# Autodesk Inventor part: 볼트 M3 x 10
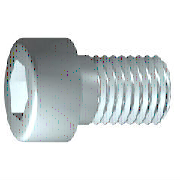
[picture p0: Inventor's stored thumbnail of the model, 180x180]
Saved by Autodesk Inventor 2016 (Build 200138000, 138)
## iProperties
Created: 2012-02
Part Number: 볼트 M3 x 10
Material: 스테인리스강
Description: 6각 소켓 머리 캡 나사
Document SubType Name: Modeling
Standard: ISO 4762
Designer: mduedu
Standard Revision: Fourth edition 2004-03-01
Standards Organization: ISO
Language: ko-KR
Size Designation: M3 x 10
Categories: <MemberInstance><Categories><Category DisplayName="조임쇠" InternalName="e4da775c-781d-43d5-af7c-5136215cf5a6" Mnemonic="FSTN"><Category DisplayName="볼트" InternalN
Density: 8.08 g/cm^3
Mass: 1.0701 g
Surface Area: 2.01851 cm^2
Volume: 0.132438 cm^3
Appearance: 반광택
IsCustomPart: 0
Author: mduedu
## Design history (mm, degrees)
sketch "스케치1"
  geometry: L1 (-0.867, 0)-(10, 0); L2 (10, 0)-(10, 1.5); L3 (10, 1.5)-(1.25, 1.5); L4 (1.25, 1.5)-(0.943, 1.5); L5 (0.943, 1.5)-(0, 1.5); L6 (0, 1.5)-(0, 2.75); L7 (0, 2.75)-(-3, 2.75); L8 (-3, 2.75)-(-3, 1.443); L9 (-3, 1.443)-(-1.7, 1.443); L10 (-1.7, 1.443)-(-0.867, 0); L11 (-5.6, 0)-(12.6, 0) reference; L12 (0, -0.55)-(0, 3.3) reference; L13 (1.25, 1.5)-(0, 1.5)
  constraints: 22 end point, 6 parallel, 2 collinear, 2 perpendicular, 1 horizontal, 1 point on line
  dimensions: "d1" = 8.75 distance from line of L3.end L2 (= GEL); "d2" = 0.30683 distance of L4.end L3.end (computed from GAL); "d3" = 3 distance between parallel lines of L8 L6 (= KOH); "d4" = 1.3 distance of L8.end L9.end (= INTI); "d5" = 60 deg angle of L10 L1; "d6" = 3 diameter of L3 L1 (= GD); "d7" = 3 diameter of L5 L1 (= BDM); "d8" = 2.88675 diameter of L9 L1 (= 1.1547 x SW); "d9" = 5.5 diameter of L7 L1 (= KOD); "d26" = 10 distance between parallel lines of L12 L2 (= NLG)
revolve "본체" sketch "스케치1" stored, may be unused: angle "d10" = 90 deg
sketch "스케치2"
  geometry: L1 (0, -3.85)-(0, 3.85) reference; L2 (-3.85, 0)-(3.85, 0) reference; L3 (1.443, 0)-(0.722, -1.25); L4 (0.722, -1.25)-(-0.722, -1.25); L5 (-0.722, -1.25)-(-1.443, 0); L6 (-1.443, 0)-(-0.722, 1.25); L7 (-0.722, 1.25)-(0.722, 1.25); L8 (0.722, 1.25)-(1.443, 0); 2 further points
  constraints: 12 end point, 1 coincident, 1 horizontal alignment, 1 point on line, 12 other
extrude "슬롯" join sketch "스케치2" stored distance "d11" = 10; taper "d12" = 0 deg
workplane "Work Plane1"
fillet "Fillet2" dims "d30" = 0.1 (= R)
body "Solid1"
fillet "모깎기1" dims "d17" = 0.3 (= RR)
feature "스레드" dims "d13" = 8.75 (= GEL), "d14" = 0
chamfer "모따기1" distance "d15" = 0.30673 (= -0.5 x SPD + 0.5 x GD); stored, may be unused: second distance "d16" = 0.30673 (= GUL), angle "d27" = 45 deg
other parameters: "GD" = 3 [user parameter; used in 2 equation terms], "NLG" = 10 [user parameter; used in 1 equation term], "GEL" = 8.75 [user parameter; used in 2 equation terms], "KOD" = 5.5 [user parameter; used in 1 equation term], "KOH" = 3 [user parameter; used in 1 equation term], "INTI" = 1.3 [user parameter; used in 1 equation term], "GAL" = 0.30673 (= 0.61345 x PTC) [user parameter; used in 1 equation term], "GUL" = 0.30673 (= 0.61345 x PTC) [user parameter; used in 1 equation term], "BDM" = 3 (= NND) [user parameter; used in 1 equation term], "SW" = 2.5 [user parameter; used in 2 equation terms], "RR" = 0.3 [user parameter; used in 1 equation term], "SPD" = 2.38655 (= NND - 1.2269 x PTC) [user parameter; used in 1 equation term], "d19" = 0, "d28" = 0, "d29" = 0, "R" = 0.1 [user parameter; used in 1 equation term], "TOA" = 30 deg [user parameter], "GD1" = 2.38655 (= THREADDIA - 1.2269 x PTC) [user parameter], "THREADDIA" = 3 [user parameter; used in 1 equation term], "FAWI" = 45 deg [user parameter], "PTC" = 0.5 [user parameter; used in 5 equation terms], "NND" = 3 [user parameter; used in 2 equation terms], "E0" = 2.8875 (= 1.155 x SW) [user parameter]
